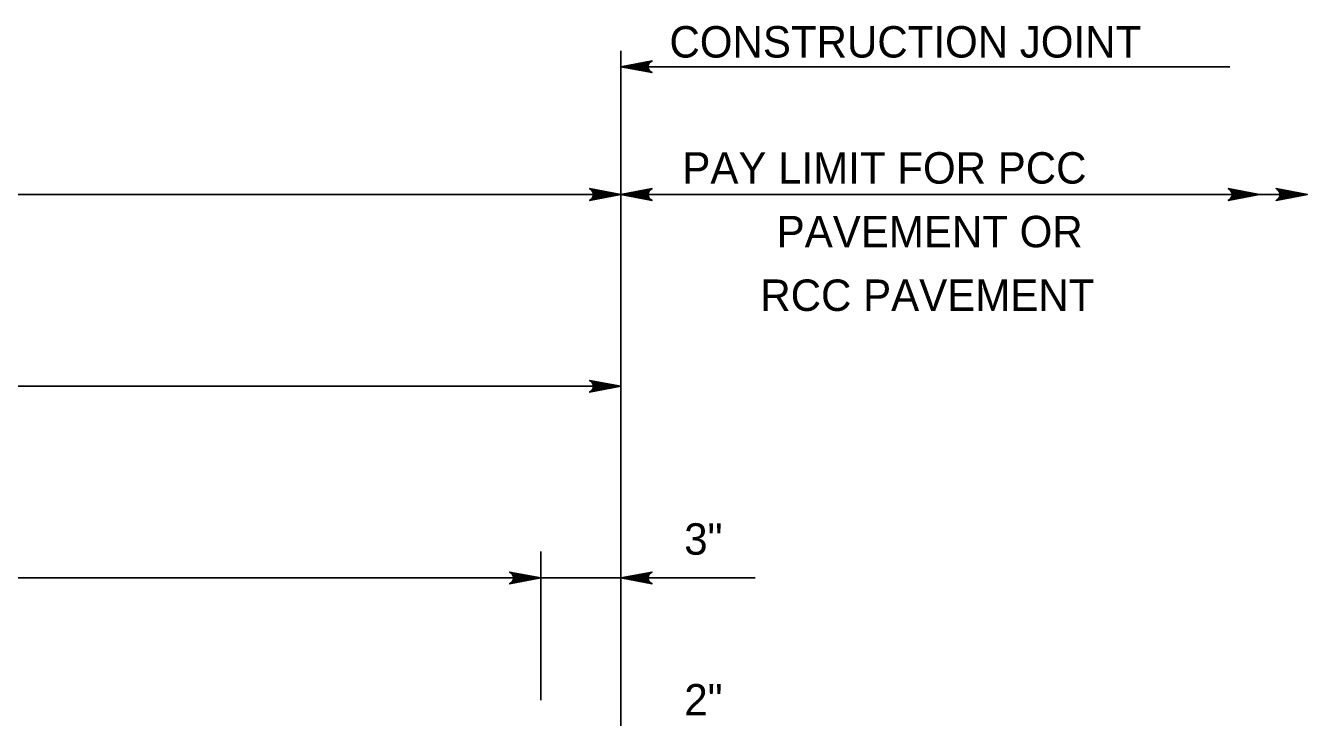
# Model space of a CAD drawing. Extents: x 2084213 to 2099800, y 976677 to 981262.
# Drawn here: x 2095516.1 to 2095917.3, y 979433.4 to 979649.9 of the extents above; entities that cross this region are included whole.
import ezdxf

# ---------------------------------------------------------------- set-up
doc = ezdxf.new("R2010")
doc.units = 0
doc.layers.add('1', color=7, linetype='Continuous')

msp = doc.modelspace()

# ---------------------------------------------------------------- linework, layer by layer
at = {"layer": '1'}
for p, q in [((2095702.37, 979349.08), (2095702.37, 979641.99)), ((2095702.37, 979637.06), (2095893.05, 979637.06)), ((2095513.76, 979597.06), (2095702.37, 979597.06)), ((2095702.37, 979597.06), (2095917.32, 979597.06)), ((2095513.76, 979537.06), (2095702.37, 979537.06)), ((2095677.37, 979438.82), (2095677.37, 979485.35)), ((2095513.76, 979477.06), (2095744.45, 979477.06))]:
    msp.add_line(p, q, dxfattribs=at)
for points in [[(2095702.37, 979637.06), (2095712.16, 979638.9), (2095711.78, 979638.63), (2095711.4, 979638.37), (2095711.21, 979638.04), (2095711.01, 979637.72), (2095710.96, 979637.39), (2095710.9, 979637.06), (2095710.96, 979636.73), (2095711.01, 979636.4), (2095711.21, 979636.08), (2095711.4, 979635.75), (2095711.78, 979635.49), (2095712.16, 979635.23), (2095702.37, 979637.06), (2095711.78, 979635.49), (2095711.4, 979635.75), (2095702.37, 979637.06), (2095711.21, 979636.08), (2095711.01, 979636.4), (2095702.37, 979637.06), (2095710.96, 979636.73), (2095710.9, 979637.06), (2095702.37, 979637.06), (2095710.96, 979637.39), (2095711.01, 979637.72), (2095702.37, 979637.06), (2095711.21, 979638.04), (2095711.4, 979638.37), (2095702.37, 979637.06), (2095711.78, 979638.63)], [(2095702.37, 979597.06), (2095692.59, 979595.23), (2095692.96, 979595.49), (2095693.34, 979595.75), (2095693.53, 979596.08), (2095693.73, 979596.4), (2095693.78, 979596.73), (2095693.84, 979597.06), (2095693.78, 979597.39), (2095693.73, 979597.72), (2095693.53, 979598.04), (2095693.34, 979598.37), (2095692.96, 979598.63), (2095692.59, 979598.9), (2095702.37, 979597.06), (2095692.96, 979598.63), (2095693.34, 979598.37), (2095702.37, 979597.06), (2095693.53, 979598.04), (2095693.73, 979597.72), (2095702.37, 979597.06), (2095693.78, 979597.39), (2095693.84, 979597.06), (2095702.37, 979597.06), (2095693.78, 979596.73), (2095693.73, 979596.4), (2095702.37, 979597.06), (2095693.53, 979596.08), (2095693.34, 979595.75), (2095702.37, 979597.06), (2095692.96, 979595.49)], [(2095702.37, 979597.06), (2095712.16, 979598.9), (2095711.78, 979598.63), (2095711.4, 979598.37), (2095711.21, 979598.04), (2095711.01, 979597.72), (2095710.96, 979597.39), (2095710.9, 979597.06), (2095710.96, 979596.73), (2095711.01, 979596.4), (2095711.21, 979596.08), (2095711.4, 979595.75), (2095711.78, 979595.49), (2095712.16, 979595.23), (2095702.37, 979597.06), (2095711.78, 979595.49), (2095711.4, 979595.75), (2095702.37, 979597.06), (2095711.21, 979596.08), (2095711.01, 979596.4), (2095702.37, 979597.06), (2095710.96, 979596.73), (2095710.9, 979597.06), (2095702.37, 979597.06), (2095710.96, 979597.39), (2095711.01, 979597.72), (2095702.37, 979597.06), (2095711.21, 979598.04), (2095711.4, 979598.37), (2095702.37, 979597.06), (2095711.78, 979598.63)], [(2095902.32, 979597.06), (2095892.54, 979598.9), (2095892.92, 979598.63), (2095893.29, 979598.37), (2095893.49, 979598.04), (2095893.68, 979597.72), (2095893.74, 979597.39), (2095893.79, 979597.06), (2095893.74, 979596.73), (2095893.68, 979596.4), (2095893.49, 979596.08), (2095893.29, 979595.75), (2095892.92, 979595.49), (2095892.54, 979595.23), (2095902.32, 979597.06), (2095892.92, 979595.49), (2095893.29, 979595.75), (2095902.32, 979597.06), (2095893.49, 979596.08), (2095893.68, 979596.4), (2095902.32, 979597.06), (2095893.74, 979596.73), (2095893.79, 979597.06), (2095902.32, 979597.06), (2095893.74, 979597.39), (2095893.68, 979597.72), (2095902.32, 979597.06), (2095893.49, 979598.04), (2095893.29, 979598.37), (2095902.32, 979597.06), (2095892.92, 979598.63)], [(2095917.32, 979597.06), (2095907.54, 979598.9), (2095907.92, 979598.63), (2095908.29, 979598.37), (2095908.49, 979598.04), (2095908.68, 979597.72), (2095908.74, 979597.39), (2095908.79, 979597.06), (2095908.74, 979596.73), (2095908.68, 979596.4), (2095908.49, 979596.08), (2095908.29, 979595.75), (2095907.92, 979595.49), (2095907.54, 979595.23), (2095917.32, 979597.06), (2095907.92, 979595.49), (2095908.29, 979595.75), (2095917.32, 979597.06), (2095908.49, 979596.08), (2095908.68, 979596.4), (2095917.32, 979597.06), (2095908.74, 979596.73), (2095908.79, 979597.06), (2095917.32, 979597.06), (2095908.74, 979597.39), (2095908.68, 979597.72), (2095917.32, 979597.06), (2095908.49, 979598.04), (2095908.29, 979598.37), (2095917.32, 979597.06), (2095907.92, 979598.63)], [(2095702.37, 979537.06), (2095692.59, 979535.23), (2095692.96, 979535.49), (2095693.34, 979535.75), (2095693.53, 979536.08), (2095693.73, 979536.4), (2095693.78, 979536.73), (2095693.84, 979537.06), (2095693.78, 979537.39), (2095693.73, 979537.72), (2095693.53, 979538.04), (2095693.34, 979538.37), (2095692.96, 979538.63), (2095692.59, 979538.9), (2095702.37, 979537.06), (2095692.96, 979538.63), (2095693.34, 979538.37), (2095702.37, 979537.06), (2095693.53, 979538.04), (2095693.73, 979537.72), (2095702.37, 979537.06), (2095693.78, 979537.39), (2095693.84, 979537.06), (2095702.37, 979537.06), (2095693.78, 979536.73), (2095693.73, 979536.4), (2095702.37, 979537.06), (2095693.53, 979536.08), (2095693.34, 979535.75), (2095702.37, 979537.06), (2095692.96, 979535.49)], [(2095677.37, 979477.06), (2095667.59, 979475.23), (2095667.96, 979475.49), (2095668.34, 979475.75), (2095668.53, 979476.08), (2095668.73, 979476.4), (2095668.78, 979476.73), (2095668.84, 979477.06), (2095668.78, 979477.39), (2095668.73, 979477.72), (2095668.53, 979478.04), (2095668.34, 979478.37), (2095667.96, 979478.63), (2095667.59, 979478.9), (2095677.37, 979477.06), (2095667.96, 979478.63), (2095668.34, 979478.37), (2095677.37, 979477.06), (2095668.53, 979478.04), (2095668.73, 979477.72), (2095677.37, 979477.06), (2095668.78, 979477.39), (2095668.84, 979477.06), (2095677.37, 979477.06), (2095668.78, 979476.73), (2095668.73, 979476.4), (2095677.37, 979477.06), (2095668.53, 979476.08), (2095668.34, 979475.75), (2095677.37, 979477.06), (2095667.96, 979475.49)], [(2095702.37, 979477.06), (2095712.16, 979478.9), (2095711.78, 979478.63), (2095711.4, 979478.37), (2095711.21, 979478.04), (2095711.01, 979477.72), (2095710.96, 979477.39), (2095710.9, 979477.06), (2095710.96, 979476.73), (2095711.01, 979476.4), (2095711.21, 979476.08), (2095711.4, 979475.75), (2095711.78, 979475.49), (2095712.16, 979475.23), (2095702.37, 979477.06), (2095711.78, 979475.49), (2095711.4, 979475.75), (2095702.37, 979477.06), (2095711.21, 979476.08), (2095711.01, 979476.4), (2095702.37, 979477.06), (2095710.96, 979476.73), (2095710.9, 979477.06), (2095702.37, 979477.06), (2095710.96, 979477.39), (2095711.01, 979477.72), (2095702.37, 979477.06), (2095711.21, 979478.04), (2095711.4, 979478.37), (2095702.37, 979477.06), (2095711.78, 979478.63)]]:
    msp.add_lwpolyline(points, dxfattribs=at)

# ---------------------------------------------------------------- texts
for s, height, p in [('CONSTRUCTION JOINT', 9.8425, (2095717.62, 979639.93)), ('PAY LIMIT FOR PCC', 9.8425, (2095721.66, 979600.47)), ('PAVEMENT OR', 9.8425, (2095751.19, 979580.55)), ('RCC PAVEMENT', 9.8425, (2095746.07, 979560.63)), ('3"', 9.843, (2095722.24, 979484.33)), ('2"', 9.843, (2095722.26, 979434.02))]:
    msp.add_text(s, height=height, dxfattribs=at).set_placement(p)

doc.saveas('drawing.dxf')
